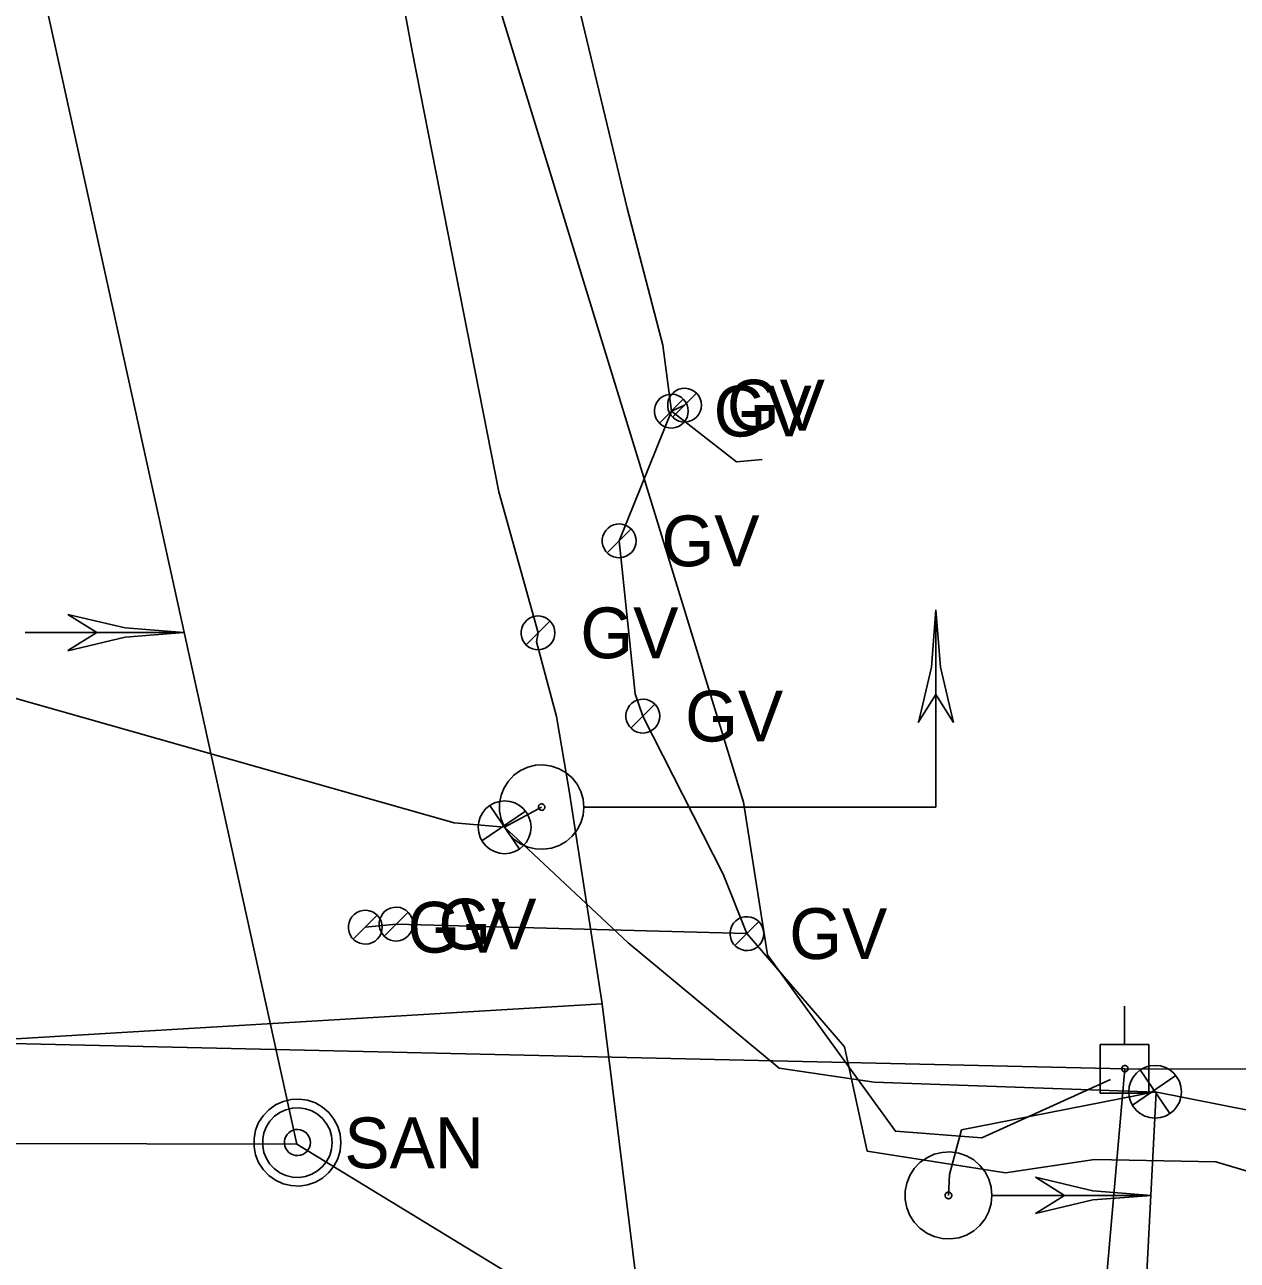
# Model space of a CAD drawing. Extents: x 600849 to 606371, y 330010 to 403088.
# Drawn here: x 605070.6 to 605162.5, y 349959.9 to 350053.6 of the extents above; entities that cross this region are included whole.
import ezdxf

# ---------------------------------------------------------------- set-up
doc = ezdxf.new("R2010")
doc.units = 0
for name, color, linetype in [('E_SIG', 7, 'Continuous'), ('E_SIG_Conduit', 7, 'Continuous'), ('E_UTL_EPowerPole', 7, 'Continuous'), ('E_UTL_G', 7, 'Continuous'), ('E_UTL_G_UG', 7, 'Continuous'), ('E_UTL_Overhead', 7, 'Continuous'), ('E_UTL_SAN', 7, 'Continuous'), ('E_UTL_SAN_UG', 7, 'Continuous'), ('E_UTL_TV_UG', 7, 'Continuous')]:
    doc.layers.add(name, color=color, linetype=linetype)

# ---------------------------------------------------------------- blocks, each defined once
blk = doc.blocks.new('_U335')
at = {"layer": 'E_SIG'}
for p, q in [((0, 6.1), (0, -6.1)), ((-6.09, 0.4), (6.1, 0.4))]:
    blk.add_line(p, q, dxfattribs=at)
blk.add_circle((0, 0.01), 6.1, dxfattribs=at)
blk = doc.blocks.new('_U354')
at = {"layer": 'E_SIG'}
for p, q in [((0, 6.1), (0, -6.1)), ((-6.09, 0.4), (6.1, 0.4))]:
    blk.add_line(p, q, dxfattribs=at)
blk.add_circle((0, 0.01), 6.1, dxfattribs=at)

msp = doc.modelspace()

# ---------------------------------------------------------------- linework, layer by layer
at = {"layer": 'E_SIG'}
for points in [[(605139.686, 350009.203), (605139.351, 350004.88), (605138.352, 350000.661)], [(605139.686, 350009.203), (605140.022, 350004.88), (605141.021, 350000.661)], [(605139.686, 349994.257), (605139.686, 350009.202)], [(605082.67, 350007.494), (605078.216, 350007.84), (605073.87, 350008.87)], [(605076.07, 350007.493), (605073.87, 350008.87)], [(605082.669, 350007.493), (605070.628, 350007.493)], [(605082.67, 350007.494), (605078.216, 350007.149), (605073.87, 350006.119)], [(605073.87, 350006.121), (605076.07, 350007.493)], [(605139.686, 350002.798), (605138.35, 350000.662)], [(605141.024, 350000.662), (605139.686, 350002.798)], [(605112.995, 349994.255), (605112.937, 349994.862), (605112.766, 349995.446), (605112.487, 349995.987), (605112.11, 349996.466), (605111.65, 349996.865), (605111.123, 349997.169), (605110.548, 349997.368), (605109.945, 349997.455), (605109.337, 349997.426), (605108.745, 349997.282), (605108.191, 349997.029), (605107.695, 349996.676), (605107.275, 349996.235), (605106.945, 349995.723), (605106.719, 349995.158), (605106.604, 349994.56), (605106.604, 349993.951), (605106.719, 349993.353), (605106.945, 349992.788), (605107.275, 349992.276), (605107.695, 349991.835), (605108.191, 349991.482), (605108.745, 349991.229), (605109.337, 349991.085), (605109.945, 349991.056), (605110.548, 349991.143), (605111.123, 349991.342), (605111.65, 349991.646), (605112.11, 349992.045), (605112.487, 349992.524), (605112.766, 349993.065), (605112.937, 349993.649), (605112.995, 349994.255)], [(605110.037, 349994.255), (605110.033, 349994.302), (605110.02, 349994.347), (605109.998, 349994.388), (605109.97, 349994.425), (605109.934, 349994.455), (605109.894, 349994.478), (605109.85, 349994.494), (605109.804, 349994.5), (605109.758, 349994.498), (605109.712, 349994.487), (605109.67, 349994.468), (605109.632, 349994.441), (605109.6, 349994.407), (605109.575, 349994.368), (605109.557, 349994.324), (605109.549, 349994.279), (605109.549, 349994.232), (605109.557, 349994.186), (605109.575, 349994.143), (605109.6, 349994.104), (605109.632, 349994.07), (605109.67, 349994.043), (605109.712, 349994.024), (605109.758, 349994.013), (605109.804, 349994.011), (605109.85, 349994.017), (605109.894, 349994.033), (605109.934, 349994.056), (605109.97, 349994.086), (605109.998, 349994.123), (605110.02, 349994.164), (605110.033, 349994.209), (605110.037, 349994.255)], [(605139.686, 349994.257), (605113.048, 349994.257)], [(605132.213, 349994.257), (605132.213, 349994.257)], [(605143.935, 349964.812), (605143.875, 349965.436), (605143.698, 349966.038), (605143.411, 349966.596), (605143.023, 349967.089), (605142.549, 349967.5), (605142.005, 349967.813), (605141.413, 349968.019), (605140.792, 349968.108), (605140.165, 349968.078), (605139.555, 349967.93), (605138.985, 349967.669), (605138.473, 349967.306), (605138.041, 349966.851), (605137.701, 349966.324), (605137.468, 349965.741), (605137.349, 349965.125), (605137.349, 349964.498), (605137.468, 349963.882), (605137.701, 349963.299), (605138.041, 349962.772), (605138.473, 349962.318), (605138.985, 349961.954), (605139.555, 349961.693), (605140.165, 349961.545), (605140.792, 349961.515), (605141.413, 349961.605), (605142.005, 349961.81), (605142.549, 349962.123), (605143.023, 349962.534), (605143.411, 349963.027), (605143.698, 349963.585), (605143.875, 349964.187), (605143.935, 349964.812)], [(605156.035, 349964.812), (605151.581, 349965.157), (605147.235, 349966.187)], [(605149.435, 349964.81), (605147.235, 349966.187)], [(605140.887, 349964.812), (605140.882, 349964.859), (605140.869, 349964.905), (605140.847, 349964.948), (605140.817, 349964.986), (605140.781, 349965.017), (605140.739, 349965.041), (605140.694, 349965.057), (605140.647, 349965.064), (605140.599, 349965.061), (605140.552, 349965.05), (605140.508, 349965.03), (605140.469, 349965.002), (605140.436, 349964.968), (605140.41, 349964.927), (605140.392, 349964.883), (605140.383, 349964.836), (605140.383, 349964.788), (605140.392, 349964.74), (605140.41, 349964.696), (605140.436, 349964.656), (605140.469, 349964.621), (605140.508, 349964.593), (605140.552, 349964.573), (605140.599, 349964.562), (605140.647, 349964.559), (605140.694, 349964.566), (605140.739, 349964.582), (605140.781, 349964.606), (605140.817, 349964.637), (605140.847, 349964.675), (605140.869, 349964.718), (605140.882, 349964.764), (605140.887, 349964.812)], [(605156.034, 349964.81), (605143.993, 349964.81)], [(605156.035, 349964.812), (605151.581, 349964.466), (605147.235, 349963.436)], [(605147.235, 349963.439), (605149.435, 349964.81)]]:
    msp.add_lwpolyline(points, dxfattribs=at)
at = {"layer": 'E_SIG_Conduit'}
for points in [[(604992.918, 349997.12), (605041.258, 350003.168), (605045.681, 350004), (605067.591, 350003.139), (605103.155, 349993.057), (605106.987, 349992.725)], [(605106.987, 349992.725), (605109.792, 349994.255)], [(605106.987, 349992.725), (605107.982, 349991.805), (605116.344, 349983.973), (605127.804, 349974.473), (605135, 349973.398), (605156.383, 349972.652)], [(605136.251, 349822.64), (605150.503, 349858.544), (605150.935, 349861.685), (605151.129, 349863.737), (605152.205, 349906.289), (605155.527, 349956.04), (605156.383, 349972.652)], [(605140.634, 349964.812), (605140.719, 349966.391), (605141.626, 349969.784), (605156.304, 349972.668)], [(605179.555, 349961.417), (605176.221, 349968.723), (605156.304, 349972.668)]]:
    msp.add_lwpolyline(points, dxfattribs=at)
at = {"layer": 'E_UTL_EPowerPole'}
for points in [[(605153.975, 349976.264), (605153.975, 349979.172)], [(605155.818, 349976.264), (605152.131, 349976.264)], [(605152.131, 349976.264), (605152.131, 349972.572)], [(605155.818, 349972.572), (605155.818, 349976.264)], [(605154.245, 349974.421), (605154.241, 349974.466), (605154.228, 349974.51), (605154.207, 349974.55), (605154.179, 349974.585), (605154.145, 349974.615), (605154.106, 349974.638), (605154.063, 349974.653), (605154.018, 349974.659), (605153.973, 349974.657), (605153.929, 349974.646), (605153.888, 349974.627), (605153.851, 349974.601), (605153.819, 349974.568), (605153.795, 349974.53), (605153.778, 349974.488), (605153.769, 349974.444), (605153.769, 349974.398), (605153.778, 349974.354), (605153.795, 349974.312), (605153.819, 349974.274), (605153.851, 349974.241), (605153.888, 349974.214), (605153.929, 349974.196), (605153.973, 349974.185), (605154.018, 349974.183), (605154.063, 349974.189), (605154.106, 349974.204), (605154.145, 349974.227), (605154.179, 349974.256), (605154.207, 349974.292), (605154.228, 349974.332), (605154.241, 349974.376), (605154.245, 349974.421)], [(605152.131, 349972.572), (605155.818, 349972.572)]]:
    msp.add_lwpolyline(points, dxfattribs=at)
at = {"layer": 'E_UTL_G'}
for points in [[(605120.908, 350024.285), (605120.885, 350024.528), (605120.816, 350024.762), (605120.704, 350024.979), (605120.554, 350025.171), (605120.369, 350025.33), (605120.158, 350025.452), (605119.927, 350025.532), (605119.686, 350025.567), (605119.442, 350025.555), (605119.205, 350025.498), (605118.983, 350025.396), (605118.784, 350025.255), (605118.616, 350025.078), (605118.484, 350024.873), (605118.393, 350024.647), (605118.347, 350024.407), (605118.347, 350024.163), (605118.393, 350023.923), (605118.484, 350023.697), (605118.616, 350023.492), (605118.784, 350023.315), (605118.983, 350023.174), (605119.205, 350023.072), (605119.442, 350023.015), (605119.686, 350023.003), (605119.927, 350023.038), (605120.158, 350023.118), (605120.369, 350023.24), (605120.554, 350023.399), (605120.704, 350023.591), (605120.816, 350023.808), (605120.885, 350024.042), (605120.908, 350024.285)], [(605118.717, 350023.378), (605120.532, 350025.192)], [(605121.908, 350024.737), (605121.885, 350024.98), (605121.816, 350025.214), (605121.704, 350025.431), (605121.554, 350025.623), (605121.369, 350025.782), (605121.158, 350025.904), (605120.927, 350025.984), (605120.686, 350026.019), (605120.442, 350026.007), (605120.205, 350025.95), (605119.983, 350025.848), (605119.784, 350025.707), (605119.616, 350025.53), (605119.484, 350025.325), (605119.393, 350025.099), (605119.347, 350024.859), (605119.347, 350024.615), (605119.393, 350024.375), (605119.484, 350024.149), (605119.616, 350023.944), (605119.784, 350023.767), (605119.983, 350023.626), (605120.205, 350023.524), (605120.442, 350023.467), (605120.686, 350023.455), (605120.927, 350023.49), (605121.158, 350023.57), (605121.369, 350023.692), (605121.554, 350023.851), (605121.704, 350024.043), (605121.816, 350024.26), (605121.885, 350024.494), (605121.908, 350024.737)], [(605119.717, 350023.83), (605121.532, 350025.644)], [(605116.949, 350014.444), (605116.926, 350014.687), (605116.857, 350014.921), (605116.745, 350015.138), (605116.595, 350015.33), (605116.41, 350015.489), (605116.199, 350015.611), (605115.968, 350015.691), (605115.727, 350015.726), (605115.483, 350015.714), (605115.246, 350015.657), (605115.024, 350015.555), (605114.825, 350015.414), (605114.657, 350015.237), (605114.525, 350015.032), (605114.434, 350014.806), (605114.388, 350014.566), (605114.388, 350014.322), (605114.434, 350014.082), (605114.525, 350013.856), (605114.657, 350013.651), (605114.825, 350013.474), (605115.024, 350013.333), (605115.246, 350013.231), (605115.483, 350013.174), (605115.727, 350013.162), (605115.968, 350013.197), (605116.199, 350013.277), (605116.41, 350013.399), (605116.595, 350013.558), (605116.745, 350013.75), (605116.857, 350013.967), (605116.926, 350014.201), (605116.949, 350014.444)], [(605114.758, 350013.537), (605116.573, 350015.351)], [(605110.802, 350007.468), (605110.779, 350007.711), (605110.71, 350007.945), (605110.598, 350008.162), (605110.448, 350008.354), (605110.263, 350008.513), (605110.052, 350008.635), (605109.821, 350008.715), (605109.58, 350008.75), (605109.336, 350008.738), (605109.099, 350008.681), (605108.877, 350008.579), (605108.678, 350008.438), (605108.51, 350008.261), (605108.378, 350008.056), (605108.287, 350007.83), (605108.241, 350007.59), (605108.241, 350007.346), (605108.287, 350007.106), (605108.378, 350006.88), (605108.51, 350006.675), (605108.678, 350006.498), (605108.877, 350006.357), (605109.099, 350006.255), (605109.336, 350006.198), (605109.58, 350006.186), (605109.821, 350006.221), (605110.052, 350006.301), (605110.263, 350006.423), (605110.448, 350006.582), (605110.598, 350006.774), (605110.71, 350006.991), (605110.779, 350007.225), (605110.802, 350007.468)], [(605108.611, 350006.561), (605110.426, 350008.375)], [(605118.743, 350001.157), (605118.72, 350001.4), (605118.651, 350001.634), (605118.539, 350001.851), (605118.389, 350002.043), (605118.204, 350002.202), (605117.993, 350002.324), (605117.762, 350002.404), (605117.521, 350002.439), (605117.277, 350002.427), (605117.04, 350002.37), (605116.818, 350002.268), (605116.619, 350002.127), (605116.451, 350001.95), (605116.319, 350001.745), (605116.228, 350001.519), (605116.182, 350001.279), (605116.182, 350001.035), (605116.228, 350000.795), (605116.319, 350000.569), (605116.451, 350000.364), (605116.619, 350000.187), (605116.818, 350000.046), (605117.04, 349999.944), (605117.277, 349999.887), (605117.521, 349999.875), (605117.762, 349999.91), (605117.993, 349999.99), (605118.204, 350000.112), (605118.389, 350000.271), (605118.539, 350000.463), (605118.651, 350000.68), (605118.72, 350000.914), (605118.743, 350001.157)], [(605116.552, 350000.25), (605118.367, 350002.064)], [(605097.705, 349985.148), (605097.682, 349985.391), (605097.613, 349985.625), (605097.501, 349985.842), (605097.351, 349986.034), (605097.166, 349986.193), (605096.955, 349986.315), (605096.724, 349986.395), (605096.483, 349986.43), (605096.239, 349986.418), (605096.002, 349986.361), (605095.78, 349986.259), (605095.581, 349986.118), (605095.413, 349985.941), (605095.281, 349985.736), (605095.19, 349985.51), (605095.144, 349985.27), (605095.144, 349985.026), (605095.19, 349984.786), (605095.281, 349984.56), (605095.413, 349984.355), (605095.581, 349984.178), (605095.78, 349984.037), (605096.002, 349983.935), (605096.239, 349983.878), (605096.483, 349983.866), (605096.724, 349983.901), (605096.955, 349983.981), (605097.166, 349984.103), (605097.351, 349984.262), (605097.501, 349984.454), (605097.613, 349984.671), (605097.682, 349984.905), (605097.705, 349985.148)], [(605095.514, 349984.241), (605097.329, 349986.055)], [(605100.037, 349985.385), (605100.014, 349985.628), (605099.945, 349985.862), (605099.833, 349986.079), (605099.683, 349986.271), (605099.498, 349986.43), (605099.287, 349986.552), (605099.056, 349986.632), (605098.815, 349986.667), (605098.571, 349986.655), (605098.334, 349986.598), (605098.112, 349986.496), (605097.913, 349986.355), (605097.745, 349986.178), (605097.613, 349985.973), (605097.522, 349985.747), (605097.476, 349985.507), (605097.476, 349985.263), (605097.522, 349985.023), (605097.613, 349984.797), (605097.745, 349984.592), (605097.913, 349984.415), (605098.112, 349984.274), (605098.334, 349984.172), (605098.571, 349984.115), (605098.815, 349984.103), (605099.056, 349984.138), (605099.287, 349984.218), (605099.498, 349984.34), (605099.683, 349984.499), (605099.833, 349984.691), (605099.945, 349984.908), (605100.014, 349985.142), (605100.037, 349985.385)], [(605097.846, 349984.478), (605099.661, 349986.292)], [(605126.639, 349984.663), (605126.616, 349984.906), (605126.547, 349985.14), (605126.435, 349985.357), (605126.285, 349985.549), (605126.1, 349985.708), (605125.889, 349985.83), (605125.658, 349985.91), (605125.417, 349985.945), (605125.173, 349985.933), (605124.936, 349985.876), (605124.714, 349985.774), (605124.515, 349985.633), (605124.347, 349985.456), (605124.215, 349985.251), (605124.124, 349985.025), (605124.078, 349984.785), (605124.078, 349984.541), (605124.124, 349984.301), (605124.215, 349984.075), (605124.347, 349983.87), (605124.515, 349983.693), (605124.714, 349983.552), (605124.936, 349983.45), (605125.173, 349983.393), (605125.417, 349983.381), (605125.658, 349983.416), (605125.889, 349983.496), (605126.1, 349983.618), (605126.285, 349983.777), (605126.435, 349983.969), (605126.547, 349984.186), (605126.616, 349984.42), (605126.639, 349984.663)], [(605124.448, 349983.756), (605126.263, 349985.57)]]:
    msp.add_lwpolyline(points, dxfattribs=at)
at = {"layer": 'E_UTL_G_UG'}
for points in [[(605125.356, 349984.663), (605123.567, 349989.16), (605117.46, 350001.157), (605116.873, 350002.845), (605115.666, 350014.444), (605119.625, 350024.285), (605118.972, 350029.285), (605116.277, 350039.677), (605112.469, 350055.591), (605107.242, 350084.587), (605104.009, 350100.921)], [(605114.391, 349979.351), (605111.866, 349995.487), (605110.919, 350001.115), (605109.392, 350006.786), (605109.519, 350007.468), (605106.542, 350018.168), (605100.012, 350051.442), (605094.141, 350083.047), (605091.346, 350096.49)], [(605119.625, 350024.285), (605120.625, 350024.737)], [(605119.625, 350024.285), (605124.564, 350020.428), (605126.507, 350020.61)], [(605096.422, 349985.148), (605098.754, 349985.385), (605125.356, 349984.663)], [(605125.356, 349984.663), (605132.761, 349976.088), (605134.479, 349968.173), (605144.956, 349966.513), (605151.708, 349967.526), (605160.898, 349967.351), (605168.137, 349965.202), (605171.969, 349962.495), (605191.688, 349960.546), (605263.595, 349959.378), (605303.765, 349959.616), (605341.687, 349958.467), (605364.553, 349957.465), (605418.621, 349955.686), (605447.684, 349956.728), (605494.963, 349954.843), (605495.122, 349948.436), (605505.72, 349947.871), (605505.71, 349947.884), (605548.569, 349947.385), (605561.023, 349949.803), (605573.828, 349948.322), (605583.219, 349947.39), (605623.719, 349945.449)], [(605039.424, 349974.865), (605114.391, 349979.351)], [(605122.711, 349691.861), (605135.038, 349706.704), (605143.619, 349720.074), (605142.416, 349734.302), (605141.577, 349746.736), (605140.161, 349761.273), (605138.912, 349774.495), (605136.949, 349797.485), (605134.93, 349816.475), (605132.498, 349848.408), (605126.902, 349882.7), (605123.425, 349906.067), (605114.391, 349979.351)]]:
    msp.add_lwpolyline(points, dxfattribs=at)
at = {"layer": 'E_UTL_Overhead'}
for points in [[(603181.1, 350033.928), (603327.139, 350030.648), (603489.534, 350051.025), (603697.713, 350051.223), (603796.188, 350042.834), (603984.486, 350028.397), (604130.286, 350016.64), (604350.169, 349999.982), (604453.047, 349992.411), (604555.194, 349985.206), (604652.233, 349982.52), (604745.216, 349980.498), (604854.735, 349979.724), (604968.564, 349978.601), (605154.007, 349974.421)], [(605143.813, 349749.735), (605140.321, 349817.891), (605154.007, 349974.421), (605253.264, 349974.254), (605333.848, 349972.876), (605354.106, 349970.796), (605513.442, 349968.286), (605659.829, 349966.499)]]:
    msp.add_lwpolyline(points, dxfattribs=at)
at = {"layer": 'E_UTL_SAN'}
for points in [[(605094.569, 349968.819), (605094.51, 349969.444), (605094.333, 349970.046), (605094.046, 349970.603), (605093.658, 349971.096), (605093.184, 349971.507), (605092.64, 349971.821), (605092.047, 349972.026), (605091.427, 349972.115), (605090.8, 349972.086), (605090.19, 349971.938), (605089.619, 349971.677), (605089.108, 349971.313), (605088.676, 349970.859), (605088.336, 349970.331), (605088.103, 349969.749), (605087.984, 349969.133), (605087.984, 349968.506), (605088.103, 349967.889), (605088.336, 349967.307), (605088.676, 349966.779), (605089.108, 349966.325), (605089.619, 349965.961), (605090.19, 349965.701), (605090.8, 349965.553), (605091.427, 349965.523), (605092.047, 349965.612), (605092.64, 349965.817), (605093.184, 349966.131), (605093.658, 349966.542), (605094.046, 349967.035), (605094.333, 349967.593), (605094.51, 349968.195), (605094.569, 349968.819)], [(605093.909, 349968.819), (605093.862, 349969.319), (605093.72, 349969.8), (605093.49, 349970.246), (605093.18, 349970.641), (605092.801, 349970.97), (605092.366, 349971.221), (605091.892, 349971.385), (605091.395, 349971.456), (605090.894, 349971.432), (605090.406, 349971.314), (605089.949, 349971.106), (605089.541, 349970.814), (605089.194, 349970.451), (605088.923, 349970.029), (605088.736, 349969.563), (605088.641, 349969.07), (605088.641, 349968.568), (605088.736, 349968.075), (605088.923, 349967.609), (605089.194, 349967.187), (605089.541, 349966.824), (605089.949, 349966.533), (605090.406, 349966.324), (605090.894, 349966.206), (605091.395, 349966.182), (605091.892, 349966.254), (605092.366, 349966.418), (605092.801, 349966.669), (605093.18, 349966.997), (605093.49, 349967.392), (605093.72, 349967.838), (605093.862, 349968.32), (605093.909, 349968.819)], [(605092.259, 349968.819), (605092.242, 349969.007), (605092.189, 349969.187), (605092.102, 349969.354), (605091.986, 349969.502), (605091.844, 349969.626), (605091.681, 349969.72), (605091.503, 349969.781), (605091.317, 349969.808), (605091.129, 349969.799), (605090.946, 349969.755), (605090.774, 349969.677), (605090.621, 349969.567), (605090.491, 349969.431), (605090.39, 349969.273), (605090.32, 349969.098), (605090.284, 349968.913), (605090.284, 349968.725), (605090.32, 349968.54), (605090.39, 349968.366), (605090.491, 349968.207), (605090.621, 349968.071), (605090.774, 349967.962), (605090.946, 349967.884), (605091.129, 349967.839), (605091.317, 349967.83), (605091.503, 349967.857), (605091.681, 349967.919), (605091.844, 349968.013), (605091.986, 349968.136), (605092.102, 349968.284), (605092.189, 349968.451), (605092.242, 349968.632), (605092.259, 349968.819)]]:
    msp.add_lwpolyline(points, dxfattribs=at)
at = {"layer": 'E_UTL_SAN_UG'}
for p, q in [((605034.547, 349968.788), (605091.219, 349968.705)), ((605091.219, 349968.705), (605145.583, 349935.602))]:
    msp.add_line(p, q, dxfattribs=at)
msp.add_lwpolyline([(605091.219, 349968.705), (605057.941, 350119.842)], dxfattribs=at)
at = {"layer": 'E_UTL_TV_UG'}
msp.add_lwpolyline([(605152.913, 349973.613), (605143.16, 349969.17), (605136.617, 349969.682), (605126.921, 349983.061), (605125.103, 349994.627), (605106.358, 350055.637), (605102.247, 350084.082)], dxfattribs=at)

# ---------------------------------------------------------------- block references
at = {"layer": 'E_SIG_Conduit', "xscale": 0.32808333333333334, "yscale": 0.3280833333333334, "rotation": 34.193210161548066}
for name, p in [('_U354', (605106.989, 349992.723)), ('_U335', (605156.304, 349972.668))]:
    msp.add_blockref(name, p, dxfattribs=at)

# ---------------------------------------------------------------- texts
at = {"layer": 'E_UTL_G'}
for p in [(605122.833, 350022.36), (605123.833, 350022.812), (605118.874, 350012.519), (605112.727, 350005.543), (605120.668, 349999.232), (605099.63, 349983.223), (605101.962, 349983.46), (605128.564, 349982.738)]:
    msp.add_text('GV', height=3.85, dxfattribs=at).set_placement(p)
at = {"layer": 'E_UTL_SAN'}
msp.add_text('SAN', height=3.8491, dxfattribs=at).set_placement((605094.833, 349966.874))

doc.saveas('drawing.dxf')
